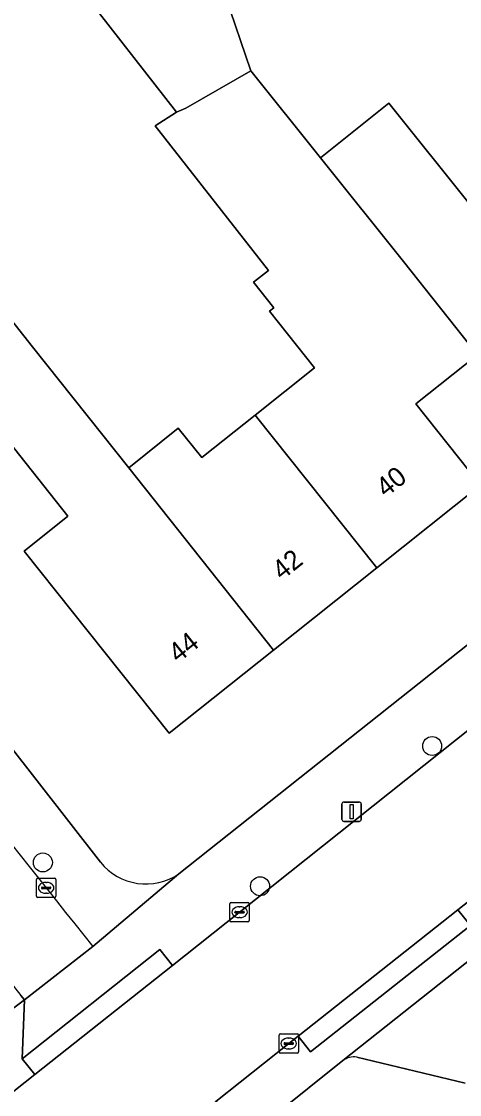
# Model space of a CAD drawing. Extents: x 159499 to 160349, y 382524 to 383273.
# Drawn here: x 159830.7 to 159853.2, y 383024.8 to 383080.1 of the extents above; entities that cross this region are included whole.
import ezdxf

# ---------------------------------------------------------------- set-up
doc = ezdxf.new("R2010")
doc.units = 0
for name, color, linetype in [('IMGEO_Boom', 7, 'Continuous'), ('IMGEO_Erf', 7, 'Continuous'), ('IMGEO_Groenvoorziening', 7, 'Continuous'), ('IMGEO_Kolk', 7, 'Continuous'), ('IMGEO_Lichtmast', 7, 'Continuous'), ('IMGEO_Pand', 7, 'Continuous'), ('IMGEO_Pand_nummerreeks', 7, 'Continuous'), ('IMGEO_Rijbaan_lokaal_open', 7, 'Continuous'), ('IMGEO_Voetpad_open', 7, 'Continuous')]:
    doc.layers.add(name, color=color, linetype=linetype)

msp = doc.modelspace()

# ---------------------------------------------------------------- linework, layer by layer
at = {"layer": 'IMGEO_Boom'}
for centre in [(159851.82, 383042.739), (159831.774, 383036.741), (159842.958, 383035.514)]:
    msp.add_circle(centre, 0.489, dxfattribs=at)
at = {"layer": 'IMGEO_Erf'}
for points in [[(159838.776, 383036.162), (160000, 383164.155)], [(159839.843, 383085.304), (159842.482, 383077.529), (159846.067, 383073.05), (159849.595, 383075.864), (159853.86, 383070.516)], [(159828.804, 383066.377), (159831.236, 383063.315), (159836.196, 383057.076), (159838.749, 383059.112), (159839.954, 383057.601), (159842.704, 383059.793), (159845.758, 383062.229), (159843.439, 383065.137), (159843.664, 383065.313), (159842.625, 383066.64), (159843.385, 383067.234), (159837.551, 383074.691), (159838.659, 383075.395), (159833.588, 383081.906)], [(159854.153, 383062.888), (159850.986, 383060.363), (159854.317, 383056.185), (159848.977, 383051.927), (159843.656, 383047.684), (159838.284, 383043.401), (159830.806, 383052.778), (159833.068, 383054.582), (159828.104, 383060.827)], [(159820.35, 383055.376), (159824.128, 383050.352), (159828.319, 383044.977), (159834.734, 383036.75)]]:
    msp.add_lwpolyline(points, dxfattribs=at)
msp.add_arc((159837.073, 383038.642), 3.009, 218.9738, 304.4724, dxfattribs=at)
at = {"layer": 'IMGEO_Groenvoorziening'}
for points in [[(159847.228, 383026.535), (159843.659, 383023.682)], [(159853.515, 383025.365), (159847.934, 383026.71)]]:
    msp.add_lwpolyline(points, dxfattribs=at)
msp.add_arc((159847.795, 383025.76), 0.96, 81.6619, 126.1813, dxfattribs=at)
at = {"layer": 'IMGEO_Kolk'}
for p, q in [((159831.444, 383035.005), (159831.444, 383035.857)), ((159831.519, 383035.931), (159832.371, 383035.931)), ((159832.445, 383035.857), (159832.445, 383035.005)), ((159831.703, 383035.425), (159831.703, 383035.437)), ((159832.141, 383035.388), (159831.743, 383035.388)), ((159831.746, 383035.474), (159832.144, 383035.474)), ((159831.932, 383035.711), (159831.957, 383035.711)), ((159832.187, 383035.437), (159832.187, 383035.425)), ((159832.371, 383034.931), (159831.519, 383034.931)), ((159831.955, 383035.151), (159831.93, 383035.151)), ((159841.402, 383033.75), (159841.402, 383034.602)), ((159841.477, 383034.676), (159842.329, 383034.676)), ((159841.661, 383034.17), (159841.661, 383034.182)), ((159841.704, 383034.219), (159842.102, 383034.219)), ((159841.89, 383034.456), (159841.915, 383034.456)), ((159842.145, 383034.182), (159842.145, 383034.17)), ((159842.403, 383034.602), (159842.403, 383033.75)), ((159842.329, 383033.676), (159841.477, 383033.676)), ((159842.099, 383034.133), (159841.701, 383034.133)), ((159841.913, 383033.896), (159841.888, 383033.896)), ((159843.934, 383026.984), (159843.934, 383027.836)), ((159844.009, 383027.91), (159844.861, 383027.91)), ((159844.422, 383027.69), (159844.447, 383027.69)), ((159844.935, 383027.836), (159844.935, 383026.984)), ((159844.193, 383027.404), (159844.193, 383027.416)), ((159844.631, 383027.367), (159844.233, 383027.367)), ((159844.236, 383027.453), (159844.634, 383027.453)), ((159844.445, 383027.13), (159844.42, 383027.13)), ((159844.677, 383027.416), (159844.677, 383027.404)), ((159844.861, 383026.91), (159844.009, 383026.91))]:
    msp.add_line(p, q, dxfattribs=at)
for points in [[(159831.444, 383035.005), (159831.444, 383035.857)], [(159831.519, 383035.931), (159832.371, 383035.931)], [(159832.445, 383035.857), (159832.445, 383035.005)], [(159832.371, 383034.931), (159831.519, 383034.931)], [(159841.402, 383033.75), (159841.402, 383034.602)], [(159841.477, 383034.676), (159842.329, 383034.676)], [(159842.403, 383034.602), (159842.403, 383033.75)], [(159842.329, 383033.676), (159841.477, 383033.676)], [(159843.934, 383026.984), (159843.934, 383027.836)], [(159844.009, 383027.91), (159844.861, 383027.91)], [(159844.935, 383027.836), (159844.935, 383026.984)], [(159844.861, 383026.91), (159844.009, 383026.91)]]:
    msp.add_lwpolyline(points, dxfattribs=at)
for centre, radius, start, end in [((159831.521, 383035.855), 0.0765, 91.552, 178.448), ((159831.521, 383035.855), 0.0765, 91.552, 178.448), ((159832.369, 383035.855), 0.0765, 1.552, 88.448), ((159832.369, 383035.855), 0.0765, 1.552, 88.448), ((159831.743, 383035.434), 0.0403, 85.8775, 175.7526), ((159831.74, 383035.424), 0.0366, 178.938, 274.7102), ((159832.144, 383035.431), 0.043, 264.8664, 352.4533), ((159832.148, 383035.436), 0.0386, 1.7309, 96.639), ((159831.521, 383035.007), 0.0765, 181.552, 268.448), ((159831.521, 383035.007), 0.0765, 181.552, 268.448), ((159832.369, 383035.007), 0.0765, 271.552, 358.448), ((159832.369, 383035.007), 0.0765, 271.552, 358.448), ((159841.479, 383034.6), 0.0765, 91.552, 178.448), ((159841.479, 383034.6), 0.0765, 91.552, 178.448), ((159841.701, 383034.179), 0.0403, 85.8775, 175.7526), ((159841.698, 383034.169), 0.0366, 178.938, 274.7102), ((159842.102, 383034.176), 0.043, 264.8664, 352.4533), ((159842.106, 383034.181), 0.0386, 1.7309, 96.639), ((159842.327, 383034.6), 0.0765, 1.552, 88.448), ((159842.327, 383034.6), 0.0765, 1.552, 88.448), ((159841.479, 383033.752), 0.0765, 181.552, 268.448), ((159841.479, 383033.752), 0.0765, 181.552, 268.448), ((159842.327, 383033.752), 0.0765, 271.552, 358.448), ((159842.327, 383033.752), 0.0765, 271.552, 358.448), ((159844.011, 383027.834), 0.0765, 91.552, 178.448), ((159844.011, 383027.834), 0.0765, 91.552, 178.448), ((159844.859, 383027.834), 0.0765, 1.552, 88.448), ((159844.859, 383027.834), 0.0765, 1.552, 88.448), ((159844.011, 383026.986), 0.0765, 181.552, 268.448), ((159844.011, 383026.986), 0.0765, 181.552, 268.448), ((159844.233, 383027.413), 0.0403, 85.8775, 175.7526), ((159844.23, 383027.403), 0.0366, 178.938, 274.7102), ((159844.634, 383027.41), 0.043, 264.8664, 352.4533), ((159844.638, 383027.415), 0.0386, 1.7309, 96.639), ((159844.859, 383026.986), 0.0765, 271.552, 358.448), ((159844.859, 383026.986), 0.0765, 271.552, 358.448)]:
    msp.add_arc(centre, radius, start, end, dxfattribs=at)
for centre, major_axis, ratio, start_param, end_param in [((159831.931, 383035.431), (-0.387, 0.002), 0.722429, 4.712389, 7.853982), ((159831.956, 383035.431), (-0.39, 0.002), 0.717154, 1.570796, 4.712389), ((159841.889, 383034.176), (-0.387, 0.002), 0.722429, 4.712389, 7.853982), ((159841.914, 383034.176), (-0.39, 0.002), 0.717154, 1.570796, 4.712389), ((159844.421, 383027.41), (-0.387, 0.002), 0.722429, 4.712389, 7.853982), ((159844.446, 383027.41), (-0.39, 0.002), 0.717154, 1.570796, 4.712389)]:
    msp.add_ellipse(centre, major_axis=major_axis, ratio=ratio, start_param=start_param, end_param=end_param, dxfattribs=at)
at = {"layer": 'IMGEO_Lichtmast'}
for p, q in [((159847.175, 383038.955), (159847.175, 383039.755)), ((159847.175, 383039.755), (159847.175, 383038.955)), ((159847.275, 383039.855), (159848.065, 383039.855)), ((159848.065, 383039.855), (159847.275, 383039.855)), ((159848.165, 383039.755), (159848.165, 383038.955)), ((159848.165, 383038.955), (159848.165, 383039.755)), ((159848.065, 383038.855), (159847.275, 383038.855)), ((159847.275, 383038.855), (159848.065, 383038.855))]:
    msp.add_line(p, q, dxfattribs=at)
msp.add_lwpolyline([(159847.595, 383039.73), (159847.745, 383039.73), (159847.745, 383038.98), (159847.595, 383038.98), (159847.595, 383039.73)], dxfattribs=at)
for centre, start, end in [((159847.275, 383039.755), 90, 180), ((159847.275, 383039.755), 90, 180), ((159848.065, 383039.755), 0, 90), ((159848.065, 383039.755), 360, 90), ((159847.275, 383038.955), 180, 270), ((159847.275, 383038.955), 180, 270), ((159848.065, 383038.955), 270, 0), ((159848.065, 383038.955), 270, 0)]:
    msp.add_arc(centre, 0.1, start, end, dxfattribs=at)
at = {"layer": 'IMGEO_Pand'}
for points in [[(159839.843, 383085.304), (159833.588, 383081.906), (159838.659, 383075.395), (159839.135, 383075.609), (159842.482, 383077.529)], [(159850.344, 383067.711), (159846.067, 383073.05), (159842.482, 383077.529), (159839.135, 383075.609), (159838.659, 383075.395), (159837.551, 383074.691), (159843.385, 383067.234), (159842.625, 383066.64), (159843.664, 383065.313), (159843.439, 383065.137), (159845.758, 383062.229), (159842.704, 383059.793), (159848.977, 383051.927), (159854.317, 383056.185), (159850.986, 383060.363), (159854.153, 383062.888)], [(159859.432, 383073.847), (159856.511, 383071.517), (159855.969, 383072.198), (159853.86, 383070.516), (159849.595, 383075.864), (159846.067, 383073.05), (159850.344, 383067.711), (159854.153, 383062.888), (159854.364, 383062.792), (159857.347, 383065.17), (159860.562, 383061.138), (159865.84, 383065.347), (159866.122, 383064.993), (159866.306, 383065.14)], [(159836.196, 383057.076), (159831.236, 383063.315), (159828.804, 383066.377), (159820.858, 383060.062), (159822.944, 383057.436), (159823.29, 383057.001), (159825.902, 383059.077), (159828.104, 383060.827), (159833.068, 383054.582), (159830.806, 383052.778), (159838.284, 383043.401), (159843.656, 383047.684)], [(159836.196, 383057.076), (159843.656, 383047.684), (159848.977, 383051.927), (159842.704, 383059.793), (159839.954, 383057.601), (159838.749, 383059.112)]]:
    msp.add_lwpolyline(points, close=True, dxfattribs=at)
at = {"layer": 'IMGEO_Rijbaan_lokaal_open'}
for points in [[(159806.004, 383071.942), (159802.113, 383078.956), (159798.193, 383076.895), (159806.265, 383062.986), (159811.901, 383054.403), (159812.215, 383053.953), (159813.072, 383052.663), (159815.684, 383048.951), (159815.85, 383048.725), (159830.638, 383029.888), (159830.825, 383029.654), (159834.352, 383032.405)], [(159855.318, 383032.955), (159847.228, 383026.535)], [(159847.934, 383026.71), (159853.515, 383025.365)]]:
    msp.add_lwpolyline(points, dxfattribs=at)
msp.add_lwpolyline([(159897.799, 383069.718), (159898.558, 383070.332), (159902.989, 383073.853), (159898.684, 383079.284), (159897.791, 383078.578), (159894.8, 383076.206), (159883.119, 383066.94), (159878.007, 383062.885), (159868.382, 383055.25), (159866.363, 383053.643), (159859.981, 383048.564), (159841.883, 383034.159), (159838.443, 383031.433), (159831.353, 383025.815), (159826.116, 383021.665), (159830.398, 383016.259), (159831.979, 383017.516), (159840.676, 383024.425), (159844.437, 383027.413), (159844.915, 383027.791), (159853.149, 383034.305), (159860.512, 383040.122)], close=True, dxfattribs=at)
for centre, radius, start, end in [((160916.425, 383895.763), 1384.294, 217.589166, 218.585443), ((159847.795, 383025.76), 0.96, 81.6619, 126.1813)]:
    msp.add_arc(centre, radius, start, end, dxfattribs=at)
at = {"layer": 'IMGEO_Voetpad_open'}
for points in [[(160003.86, 383167.245), (160000, 383164.155), (159838.776, 383036.162), (159834.352, 383032.405), (159830.825, 383029.654), (159830.707, 383026.63), (159837.797, 383032.248), (159838.443, 383031.433), (159841.883, 383034.159), (159859.981, 383048.564)], [(159860.512, 383040.122), (159853.149, 383034.305), (159853.794, 383033.489), (159845.56, 383026.975), (159844.915, 383027.791), (159844.437, 383027.413), (159840.676, 383024.425), (159841.323, 383023.611), (159837.225, 383020.355), (159838.065, 383019.297), (159840.782, 383021.442), (159843.659, 383023.682), (159847.228, 383026.535), (159855.318, 383032.955), (159879.615, 383052.244), (159882.241, 383048.977), (159884.082, 383050.481), (159881.522, 383053.674), (159905.827, 383073.006)], [(159834.734, 383036.75), (159828.319, 383044.977)], [(159834.352, 383032.405), (159838.776, 383036.162)], [(159824.858, 383025.202), (159824.98, 383025.268), (159830.825, 383029.654), (159830.638, 383029.888)]]:
    msp.add_lwpolyline(points, dxfattribs=at)
for points in [[(159844.915, 383027.791), (159845.56, 383026.975), (159853.794, 383033.489), (159853.149, 383034.305)], [(159831.353, 383025.815), (159838.443, 383031.433), (159837.797, 383032.248), (159830.707, 383026.63)], [(159823.977, 383019.969), (159826.116, 383021.665), (159831.353, 383025.815), (159830.707, 383026.63), (159830.825, 383029.654), (159824.98, 383025.268), (159824.858, 383025.202), (159793.053, 383000), (159774.942, 382985.649), (159777.025, 382982.921), (159782.608, 382987.234), (159788.426, 382991.835), (159787.781, 382992.651), (159793.432, 382997.12), (159794.077, 382996.304), (159794.355, 382996.523), (159798.752, 383000), (159805.481, 383005.321), (159804.836, 383006.137), (159809.927, 383010.163), (159810.572, 383009.347)]]:
    msp.add_lwpolyline(points, close=True, dxfattribs=at)
for centre, radius, start, end in [((160916.425, 383895.763), 1384.294, 217.589166, 218.585443), ((159837.073, 383038.642), 3.009, 218.9738, 304.4724)]:
    msp.add_arc(centre, radius, start, end, dxfattribs=at)

# ---------------------------------------------------------------- texts
at = {"layer": 'IMGEO_Pand_nummerreeks'}
for s, rotation, p in [('40', 38.5658, (159849.43, 383055.512)), ('42', 38.5673, (159844.082, 383051.246)), ('44', 38.5658, (159838.738, 383046.987))]:
    msp.add_text(s, height=1, rotation=rotation, dxfattribs=at).set_placement(p)

doc.saveas('drawing.dxf')
